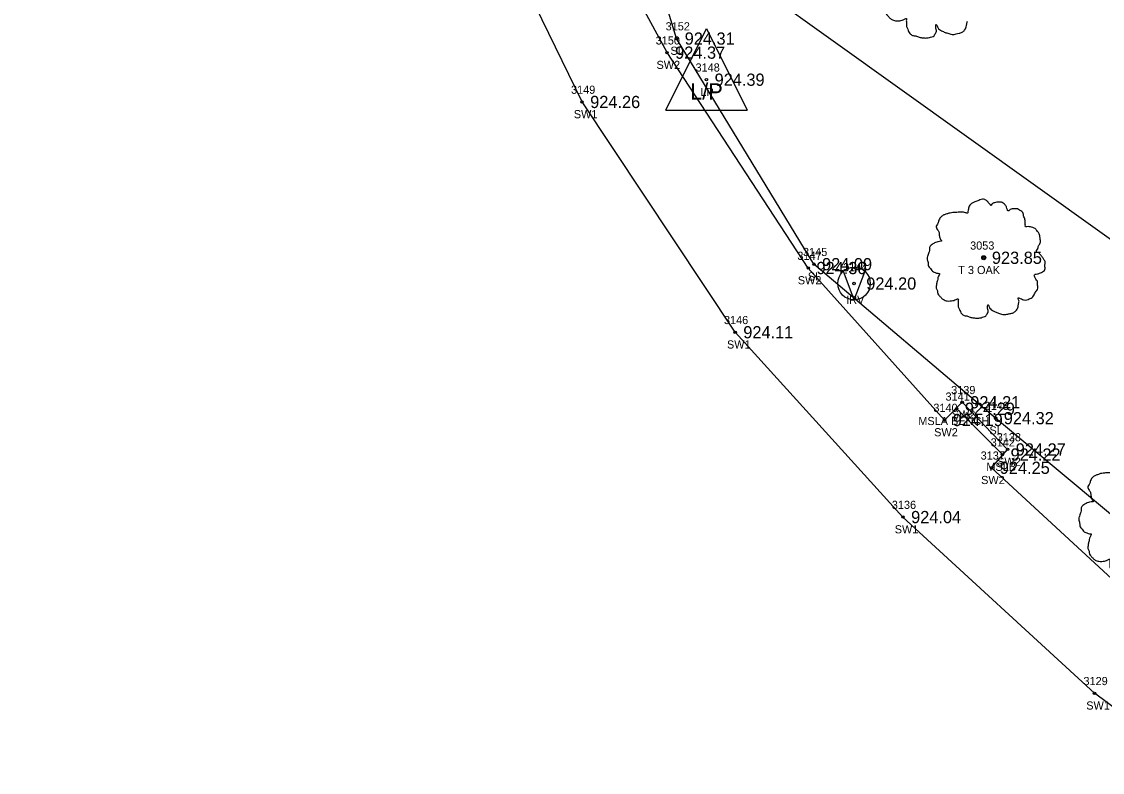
# Model space of a CAD drawing. Extents: x 1575382 to 1578175, y 1099175 to 1101955.
# Drawn here: x 1576698 to 1576830.6, y 1100913.3 to 1101005.4 of the extents above; entities that cross this region are included whole.
import ezdxf

# ---------------------------------------------------------------- set-up
doc = ezdxf.new("R2010")
doc.units = 0
for name, color, linetype in [('RD_EX_BldgApp', 7, 'Continuous'), ('RD_EX_Conc', 7, 'Continuous'), ('RD_EX_Conc_txCode', 7, 'Continuous'), ('RD_EX_Misc', 7, 'Continuous'), ('RD_EX_Misc_txCode', 7, 'Continuous'), ('RD_EX_TX_Conc_ELEV', 7, 'Continuous'), ('RD_EX_TX_Misc_ELEV', 7, 'Continuous'), ('RD_EX_TX_UT_ELEV', 7, 'Continuous'), ('RD_EX_TX_VEG_ELEV', 7, 'Continuous'), ('RD_EX_UT', 7, 'Continuous'), ('RD_EX_UT_txCode', 7, 'Continuous'), ('RD_EX_VEG', 7, 'Continuous'), ('RD_EX_VEG_txCode', 7, 'Continuous'), ('RD_HC_Cl', 7, 'Continuous'), ('RD_SMD_Locator', 7, 'Continuous')]:
    doc.layers.add(name, color=color, linetype=linetype)

msp = doc.modelspace()

# ---------------------------------------------------------------- linework, layer by layer
at = {"layer": 'RD_EX_BldgApp'}
for q in [(1576798.84, 1100974.78), (1576801.47, 1100974.74)]:
    msp.add_line((1576800.14, 1100971.29), q, dxfattribs=at)
for radius in [2, 0.15]:
    msp.add_circle((1576800.14, 1100973.29), radius, dxfattribs=at)
at = {"layer": 'RD_EX_Conc'}
for points in [[(1576833.92, 1100935.07), (1576817.03, 1100950.68), (1576818.99, 1100952.93), (1576813.41, 1100958.72), (1576811.26, 1100956.54), (1576794.53, 1100975.19), (1576777.19, 1101001.62), (1576770.51, 1101013.97), (1576773.31, 1101015.41), (1576769.88, 1101022.74), (1576767.19, 1101021.23), (1576757.57, 1101042.29), (1576760.46, 1101043.4), (1576757.26, 1101050.95), (1576754.31, 1101049.74), (1576748.41, 1101072), (1576751.65, 1101072.71), (1576749.83, 1101080.61), (1576746.77, 1101079.95), (1576732.47, 1101128.5)], [(1576905.5, 1100784.02), (1576906.93, 1100800.36), (1576903.94, 1100824.42), (1576891.57, 1100857.98), (1576873.27, 1100886.93), (1576851.85, 1100906.5), (1576829.65, 1100923.01), (1576806.15, 1100944.63), (1576785.55, 1100967.31), (1576766.76, 1100995.57), (1576746.33, 1101037.55), (1576735.06, 1101077.23), (1576721.04, 1101124.3)]]:
    msp.add_lwpolyline(points, dxfattribs=at)
at = {"layer": 'RD_EX_Misc'}
msp.add_line((1576812.75, 1100957.92), (1576818.35, 1100952.3), dxfattribs=at)
at = {"layer": 'RD_EX_UT'}
for p, q in [((1576777.03, 1100994.58), (1576782.03, 1101004.58)), ((1576782.03, 1101004.58), (1576787.03, 1100994.58)), ((1576777.03, 1100994.58), (1576787.03, 1100994.58))]:
    msp.add_line(p, q, dxfattribs=at)
msp.add_lwpolyline([(1576697.98, 1101074.32), (1577079.49, 1100801.52), (1576931.93, 1100529.3), (1577183.5, 1100413.67)], dxfattribs=at)
at = {"layer": 'RD_EX_VEG'}
msp.add_lwpolyline([(1576864.83, 1100917.25), (1576817.52, 1100956.77), (1576795.22, 1100975.66), (1576778.36, 1101003.35), (1576773.36, 1101019.82), (1576751.68, 1101077.49), (1576733.46, 1101130.12)], dxfattribs=at)
for centre, radius in [((1576816.06, 1100976.45), 0.25), ((1576816.05, 1100976.43), 0.0001)]:
    msp.add_circle(centre, radius, dxfattribs=at)
for points in [[(1576809.84, 1101017.99), (1576809.54, 1101018.01), (1576809.21, 1101017.91), (1576808.96, 1101017.81), (1576808.74, 1101017.74), (1576808.51, 1101017.64), (1576808.21, 1101017.46), (1576807.99, 1101017.26), (1576807.86, 1101017.01), (1576807.81, 1101016.79), (1576807.76, 1101016.51), (1576807.76, 1101016.34), (1576807.64, 1101016.31), (1576807.49, 1101016.34), (1576807.24, 1101016.41), (1576806.99, 1101016.41), (1576806.74, 1101016.41), (1576806.39, 1101016.39), (1576806.04, 1101016.39), (1576805.76, 1101016.34), (1576805.44, 1101016.29), (1576805.06, 1101016.16), (1576804.71, 1101016.04), (1576804.41, 1101015.79), (1576804.16, 1101015.31), (1576804.04, 1101014.96), (1576803.89, 1101014.71), (1576804.04, 1101014.26), (1576804.21, 1101013.91), (1576804.24, 1101013.71), (1576804.31, 1101013.29), (1576804.41, 1101013.06), (1576804.54, 1101012.86), (1576804.46, 1101012.84), (1576804.09, 1101012.79), (1576803.79, 1101012.69), (1576803.36, 1101012.46), (1576803.14, 1101012.24), (1576803.04, 1101011.92), (1576803.01, 1101011.57), (1576802.91, 1101011.37), (1576802.84, 1101011.09), (1576802.81, 1101011.02), (1576802.76, 1101010.69), (1576802.86, 1101010.24), (1576802.89, 1101009.89), (1576803.01, 1101009.67), (1576803.16, 1101009.49), (1576803.34, 1101009.24), (1576803.74, 1101009.02), (1576804.06, 1101008.92), (1576804.26, 1101008.89), (1576804.09, 1101008.39), (1576804.04, 1101008.04), (1576803.91, 1101007.64), (1576803.91, 1101007.57), (1576803.86, 1101007.09), (1576804.01, 1101006.77), (1576804.09, 1101006.39), (1576804.26, 1101006.17), (1576804.54, 1101005.87), (1576804.86, 1101005.64), (1576805.36, 1101005.52), (1576805.76, 1101005.54), (1576806.34, 1101005.72), (1576806.59, 1101005.79), (1576806.56, 1101005.62), (1576806.59, 1101005.24), (1576806.59, 1101004.82), (1576806.74, 1101004.49), (1576806.84, 1101004.22), (1576806.99, 1101003.97), (1576807.31, 1101003.74), (1576807.71, 1101003.67), (1576808.14, 1101003.52), (1576808.59, 1101003.44), (1576809.09, 1101003.42), (1576809.69, 1101003.57), (1576809.96, 1101003.69), (1576810.06, 1101003.87), (1576810.26, 1101004.24), (1576810.21, 1101004.47), (1576810.24, 1101005.07), (1576810.34, 1101004.89), (1576810.51, 1101004.54), (1576811.01, 1101004.24), (1576811.41, 1101004.07), (1576811.88, 1101003.92), (1576812.18, 1101003.84), (1576812.66, 1101003.92), (1576813.03, 1101003.99), (1576813.41, 1101004.12), (1576813.71, 1101004.39), (1576813.88, 1101004.67), (1576813.93, 1101004.94), (1576814.01, 1101005.32), (1576814.06, 1101005.49)], [(1576816.19, 1100983.61), (1576815.89, 1100983.64), (1576815.57, 1100983.54), (1576815.32, 1100983.44), (1576815.09, 1100983.36), (1576814.87, 1100983.26), (1576814.57, 1100983.09), (1576814.34, 1100982.89), (1576814.22, 1100982.64), (1576814.17, 1100982.41), (1576814.12, 1100982.14), (1576814.12, 1100981.96), (1576813.99, 1100981.94), (1576813.84, 1100981.96), (1576813.59, 1100982.04), (1576813.34, 1100982.04), (1576813.09, 1100982.04), (1576812.74, 1100982.01), (1576812.39, 1100982.01), (1576812.12, 1100981.96), (1576811.79, 1100981.91), (1576811.42, 1100981.79), (1576811.07, 1100981.66), (1576810.77, 1100981.41), (1576810.52, 1100980.94), (1576810.39, 1100980.59), (1576810.24, 1100980.34), (1576810.39, 1100979.89), (1576810.57, 1100979.54), (1576810.59, 1100979.34), (1576810.67, 1100978.91), (1576810.77, 1100978.69), (1576810.89, 1100978.49), (1576810.82, 1100978.47), (1576810.44, 1100978.42), (1576810.14, 1100978.32), (1576809.72, 1100978.09), (1576809.49, 1100977.87), (1576809.39, 1100977.54), (1576809.37, 1100977.19), (1576809.27, 1100976.99), (1576809.19, 1100976.72), (1576809.17, 1100976.64), (1576809.12, 1100976.32), (1576809.22, 1100975.87), (1576809.24, 1100975.52), (1576809.37, 1100975.29), (1576809.52, 1100975.12), (1576809.69, 1100974.87), (1576810.09, 1100974.64), (1576810.42, 1100974.54), (1576810.62, 1100974.52), (1576810.44, 1100974.02), (1576810.39, 1100973.67), (1576810.27, 1100973.27), (1576810.27, 1100973.19), (1576810.22, 1100972.72), (1576810.37, 1100972.39), (1576810.44, 1100972.02), (1576810.62, 1100971.79), (1576810.89, 1100971.49), (1576811.22, 1100971.27), (1576811.72, 1100971.14), (1576812.12, 1100971.17), (1576812.69, 1100971.34), (1576812.94, 1100971.42), (1576812.92, 1100971.24), (1576812.94, 1100970.87), (1576812.94, 1100970.44), (1576813.09, 1100970.12), (1576813.19, 1100969.84), (1576813.34, 1100969.59), (1576813.67, 1100969.37), (1576814.07, 1100969.29), (1576814.49, 1100969.14), (1576814.94, 1100969.07), (1576815.44, 1100969.04), (1576816.04, 1100969.19), (1576816.32, 1100969.32), (1576816.42, 1100969.49), (1576816.62, 1100969.87), (1576816.57, 1100970.09), (1576816.59, 1100970.69), (1576816.69, 1100970.52), (1576816.87, 1100970.17), (1576817.37, 1100969.87), (1576817.77, 1100969.69), (1576818.24, 1100969.54), (1576818.54, 1100969.47), (1576819.01, 1100969.54), (1576819.39, 1100969.62), (1576819.76, 1100969.74), (1576820.06, 1100970.02), (1576820.24, 1100970.29), (1576820.29, 1100970.57), (1576820.36, 1100970.94), (1576820.41, 1100971.12)], [(1576820.41, 1100971.12), (1576820.34, 1100971.29), (1576820.29, 1100971.54), (1576820.36, 1100971.52), (1576820.54, 1100971.47), (1576820.81, 1100971.34), (1576821.04, 1100971.27), (1576821.36, 1100971.29), (1576821.64, 1100971.39), (1576822.09, 1100971.67), (1576822.36, 1100972.14), (1576822.64, 1100972.54), (1576822.71, 1100972.87), (1576822.66, 1100973.09), (1576822.64, 1100973.59), (1576822.44, 1100973.84), (1576822.39, 1100973.97), (1576822.29, 1100974.37), (1576822.36, 1100974.42), (1576822.64, 1100974.47), (1576823.01, 1100974.59), (1576823.29, 1100974.72), (1576823.51, 1100974.89), (1576823.59, 1100975.12), (1576823.56, 1100975.52), (1576823.61, 1100975.92), (1576823.54, 1100976.07), (1576823.44, 1100976.22), (1576823.36, 1100976.42), (1576823.21, 1100976.57), (1576823.11, 1100976.72), (1576823.01, 1100976.82), (1576822.89, 1100976.97), (1576822.71, 1100977.09), (1576822.56, 1100977.14), (1576822.51, 1100977.29), (1576822.66, 1100977.49), (1576822.71, 1100977.59), (1576822.74, 1100977.82), (1576822.96, 1100978.17), (1576823.01, 1100978.57), (1576822.96, 1100978.99), (1576822.91, 1100979.26), (1576822.76, 1100979.54), (1576822.56, 1100979.79), (1576822.44, 1100979.96), (1576822.26, 1100980.09), (1576821.94, 1100980.21), (1576821.69, 1100980.26), (1576821.34, 1100980.26), (1576821.14, 1100980.31), (1576821.16, 1100980.36), (1576821.16, 1100980.51), (1576821.16, 1100980.79), (1576821.09, 1100981.24), (1576820.94, 1100981.74), (1576820.94, 1100981.76), (1576820.84, 1100982.01), (1576820.61, 1100982.21), (1576820.44, 1100982.31), (1576820.24, 1100982.44), (1576819.99, 1100982.46), (1576819.69, 1100982.46), (1576819.41, 1100982.41), (1576819.21, 1100982.31), (1576819.04, 1100982.19), (1576818.96, 1100982.34), (1576818.86, 1100982.64), (1576818.81, 1100982.79), (1576818.67, 1100982.96), (1576818.44, 1100983.16), (1576817.99, 1100983.29), (1576817.37, 1100983.21), (1576817.07, 1100983.01), (1576816.92, 1100982.84), (1576816.87, 1100982.96), (1576816.67, 1100983.16), (1576816.57, 1100983.34), (1576816.39, 1100983.46), (1576816.24, 1100983.56), (1576816.14, 1100983.61)], [(1576834.8, 1100951.65), (1576834.5, 1100951.68), (1576834.18, 1100951.58), (1576833.93, 1100951.48), (1576833.7, 1100951.41), (1576833.48, 1100951.31), (1576833.18, 1100951.13), (1576832.95, 1100950.93), (1576832.83, 1100950.68), (1576832.78, 1100950.46), (1576832.73, 1100950.18), (1576832.73, 1100950.01), (1576832.6, 1100949.98), (1576832.45, 1100950.01), (1576832.2, 1100950.08), (1576831.95, 1100950.08), (1576831.7, 1100950.08), (1576831.35, 1100950.06), (1576831, 1100950.06), (1576830.73, 1100950.01), (1576830.4, 1100949.96), (1576830.03, 1100949.83), (1576829.68, 1100949.71), (1576829.38, 1100949.46), (1576829.13, 1100948.98), (1576829, 1100948.63), (1576828.85, 1100948.38), (1576829, 1100947.93), (1576829.18, 1100947.58), (1576829.2, 1100947.38), (1576829.28, 1100946.96), (1576829.38, 1100946.73), (1576829.5, 1100946.53), (1576829.43, 1100946.51), (1576829.05, 1100946.46), (1576828.75, 1100946.36), (1576828.33, 1100946.13), (1576828.1, 1100945.91), (1576828, 1100945.58), (1576827.98, 1100945.23), (1576827.88, 1100945.03), (1576827.81, 1100944.76), (1576827.78, 1100944.68), (1576827.73, 1100944.36), (1576827.83, 1100943.91), (1576827.86, 1100943.56), (1576827.98, 1100943.33), (1576828.13, 1100943.16), (1576828.3, 1100942.91), (1576828.7, 1100942.68), (1576829.03, 1100942.58), (1576829.23, 1100942.56), (1576829.05, 1100942.06), (1576829, 1100941.71), (1576828.88, 1100941.31), (1576828.88, 1100941.23), (1576828.83, 1100940.76), (1576828.98, 1100940.43), (1576829.05, 1100940.06), (1576829.23, 1100939.84), (1576829.5, 1100939.54), (1576829.83, 1100939.31), (1576830.33, 1100939.19), (1576830.73, 1100939.21), (1576831.3, 1100939.39), (1576831.55, 1100939.46), (1576831.53, 1100939.29), (1576831.55, 1100938.91), (1576831.55, 1100938.49), (1576831.7, 1100938.16), (1576831.8, 1100937.89), (1576831.95, 1100937.64), (1576832.28, 1100937.41), (1576832.68, 1100937.34), (1576833.1, 1100937.19), (1576833.55, 1100937.11), (1576834.05, 1100937.09), (1576834.65, 1100937.24), (1576834.93, 1100937.36), (1576835.03, 1100937.54), (1576835.23, 1100937.91), (1576835.18, 1100938.14), (1576835.2, 1100938.74), (1576835.3, 1100938.56), (1576835.48, 1100938.21), (1576835.98, 1100937.91), (1576836.38, 1100937.74), (1576836.85, 1100937.59), (1576837.15, 1100937.51), (1576837.63, 1100937.59), (1576838, 1100937.66), (1576838.38, 1100937.79), (1576838.68, 1100938.06), (1576838.85, 1100938.34), (1576838.9, 1100938.61), (1576838.98, 1100938.99), (1576839.03, 1100939.16)]]:
    msp.add_spline(points, degree=3, dxfattribs=at)
at = {"layer": 'RD_HC_Cl'}
msp.add_arc((1577257.91, 1101196.45), 450, 194.1013, 235.1317, dxfattribs=at)
at = {"layer": 'RD_SMD_Locator'}
for centre in [(1576778.36, 1101003.35), (1576777.19, 1101001.62), (1576782.03, 1100998.3), (1576766.76, 1100995.57), (1576795.22, 1100975.66), (1576816.06, 1100976.45), (1576794.53, 1100975.19), (1576785.55, 1100967.31), (1576813.41, 1100958.72), (1576812.75, 1100957.92), (1576817.52, 1100956.77), (1576811.26, 1100956.54), (1576818.99, 1100952.93), (1576818.35, 1100952.3), (1576817.03, 1100950.68), (1576806.15, 1100944.63), (1576829.65, 1100923.01)]:
    msp.add_circle(centre, 0.15, dxfattribs=at)

# ---------------------------------------------------------------- texts
at = {"layer": 'RD_EX_Conc_txCode'}
for s, p in [('3150', (1576775.8, 1101002.62)), ('SW2', (1576775.9, 1100999.62)), ('3149', (1576765.41, 1100996.57)), ('SW1', (1576765.75, 1100993.57)), ('3147', (1576793.19, 1100976.19)), ('SW2', (1576793.24, 1100973.19)), ('3146', (1576784.18, 1100968.31)), ('SW1', (1576784.55, 1100965.31)), ('3139', (1576812.06, 1100959.72)), ('3140', (1576809.88, 1100957.54)), ('SW2', (1576812.12, 1100956.72)), ('SW2', (1576809.97, 1100954.54)), ('3138', (1576817.65, 1100953.93)), ('3137', (1576815.68, 1100951.68)), ('SW2', (1576817.7, 1100950.93)), ('SW2', (1576815.74, 1100948.68)), ('3136', (1576804.78, 1100945.63)), ('SW1', (1576805.14, 1100942.63)), ('3129', (1576828.3, 1100924.01)), ('SW1', (1576828.64, 1100921.01))]:
    msp.add_text(s, height=1, dxfattribs=at).set_placement(p)
at = {"layer": 'RD_EX_Misc_txCode'}
for s, p in [('3144', (1576798.8, 1100974.79)), ('IRV', (1576799.18, 1100970.79)), ('3141', (1576811.37, 1100958.92)), ('MSLA BENCH', (1576808.03, 1100955.92)), ('3142', (1576816.91, 1100953.3)), ('MSLB', (1576816.38, 1100950.3))]:
    msp.add_text(s, height=1, dxfattribs=at).set_placement(p)
at = {"layer": 'RD_EX_TX_Conc_ELEV'}
for s, p in [('924.37', (1576778.19, 1101000.87)), ('924.26', (1576767.76, 1100994.82)), ('924.30', (1576795.53, 1100974.44)), ('924.11', (1576786.55, 1100966.56)), ('924.21', (1576814.41, 1100957.97)), ('924.19', (1576812.26, 1100955.79)), ('924.27', (1576819.99, 1100952.18)), ('924.25', (1576818.03, 1100949.93)), ('924.04', (1576807.15, 1100943.88))]:
    msp.add_text(s, height=1.5, dxfattribs=at).set_placement(p)
at = {"layer": 'RD_EX_TX_Misc_ELEV'}
for s, p in [('924.20', (1576801.64, 1100972.54)), ('924.29', (1576813.75, 1100957.17)), ('924.22', (1576819.35, 1100951.55))]:
    msp.add_text(s, height=1.5, dxfattribs=at).set_placement(p)
at = {"layer": 'RD_EX_TX_UT_ELEV'}
msp.add_text('924.39', height=1.5, dxfattribs=at).set_placement((1576783.03, 1100997.55))
at = {"layer": 'RD_EX_TX_VEG_ELEV'}
for s, p in [('924.31', (1576779.36, 1101002.6)), ('923.85', (1576817.06, 1100975.7)), ('924.09', (1576796.22, 1100974.91)), ('924.32', (1576818.52, 1100956.02))]:
    msp.add_text(s, height=1.5, dxfattribs=at).set_placement(p)
at = {"layer": 'RD_EX_UT'}
msp.add_text('L/P', height=2, dxfattribs=at).set_placement((1576780.02, 1100995.86))
at = {"layer": 'RD_EX_UT_txCode'}
for s, p in [('3148', (1576780.69, 1100999.3)), ('LP', (1576781.28, 1100996.3))]:
    msp.add_text(s, height=1, dxfattribs=at).set_placement(p)
at = {"layer": 'RD_EX_VEG_txCode'}
for s, p in [('3152', (1576777.02, 1101004.35)), ('SL', (1576777.61, 1101001.35)), ('3053', (1576814.39, 1100977.45)), ('3145', (1576793.88, 1100976.66)), ('T 3 OAK', (1576812.93, 1100974.45)), ('SL', (1576794.47, 1100973.66)), ('3143', (1576816.17, 1100957.77)), ('SL', (1576816.76, 1100954.77))]:
    msp.add_text(s, height=1, dxfattribs=at).set_placement(p)

doc.saveas('drawing.dxf')
